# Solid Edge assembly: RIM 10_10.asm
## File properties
Title: Zylinder
Author: ahadarics
Template: iso metric assembly.asm
Last saved by: psaghy
Revision: 4
Application: Solid Edge
Username: ahadarics
Dokumentum tartalom típus: 1
Document Number: RIM 10/10
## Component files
Kit_2.par
Profilrohr.par
Kit_1.par
Kolbenstange.par
Mutter_1.par
Mutter_2.par
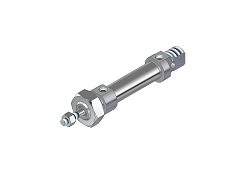
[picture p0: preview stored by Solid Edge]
